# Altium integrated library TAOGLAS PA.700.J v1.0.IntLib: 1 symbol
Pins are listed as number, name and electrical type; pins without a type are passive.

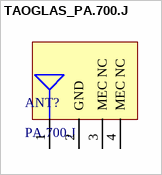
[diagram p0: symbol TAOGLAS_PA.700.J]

## TAOGLAS_PA.700.J
designator ANT?, comment PA.700.J
Samurai Hexa-Band Cellular SMD Antenna; ComponentLibStatus: Created; MFG: Taoglas; Temp_High: +85C; Temp_Low: -40C
footprint TAOGLAS_PA.700.J (Samurai Hexa-Band Cellular SMD Antenna)
pins: 1 RF OUT, 2 GND, 3 MEC NC, 4 MEC NC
